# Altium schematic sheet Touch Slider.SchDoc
size A4; Revision: B.2
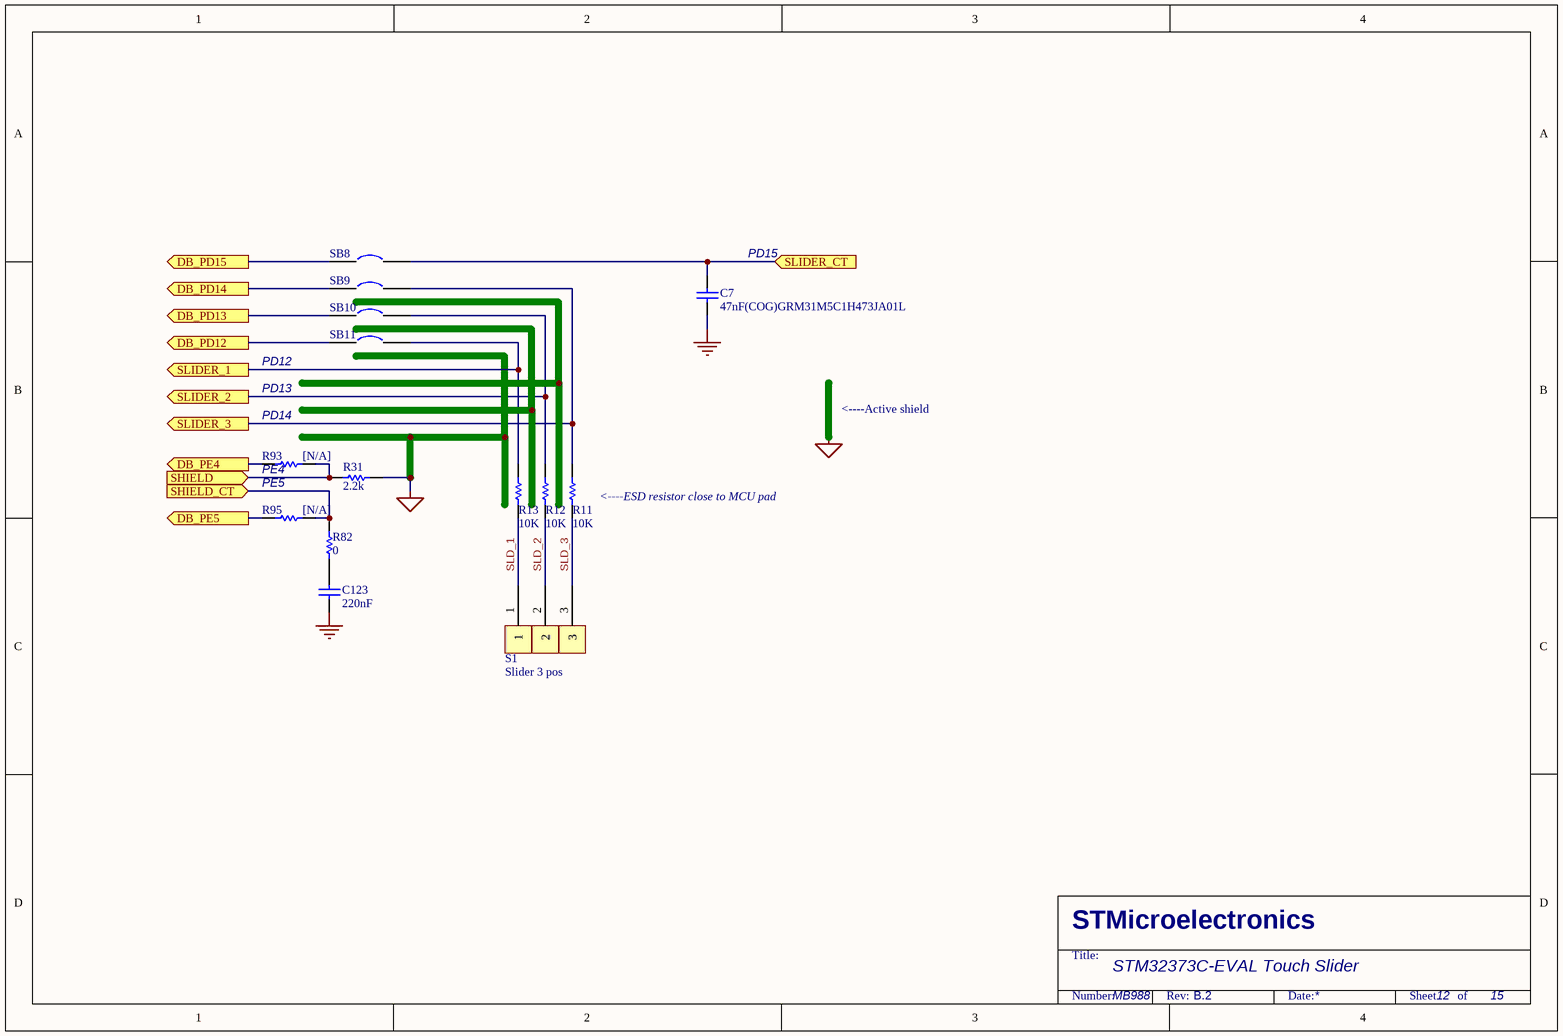
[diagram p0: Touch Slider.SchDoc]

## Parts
C7  47nF(COG)GRM31M5C1H473JA01L  [1206C]
C123  220nF  [0603C]
R11  10K  [0603R]
R12  10K  [0603R]
R13  10K  [0603R]
R31  2.2k  [0603R]
R82  0  [0603R]
R93  [N/A]  [0603R]
R95  [N/A]  [0603R]
S1  Slider 3 pos  [SLIDER3-2(50)]
SB8  (no value)  [JP2_SMD]
SB9  (no value)  [JP2_SMD]
SB10  (no value)  [JP2_SMD]
SB11  (no value)  [JP2_SMD]

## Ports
DB_PD12 (out), DB_PD13 (out), DB_PD14 (out), DB_PD15 (out), DB_PE4 (out), DB_PE5 (out), SHIELD (in), SHIELD_CT (in), SLIDER_1 (out), SLIDER_2 (out), SLIDER_3 (out), SLIDER_CT (in)

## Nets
GND: C7.1 C123.1
TS_SHIELD: R31.2
DB_PD12: SB11.1 ; port DB_PD12
DB_PD13: SB10.1 ; port DB_PD13
DB_PD14: SB9.1 ; port DB_PD14
DB_PD15: SB8.1 ; port DB_PD15
DB_PE4: R93.2 ; port DB_PE4
DB_PE5: R95.2 ; port DB_PE5
SHIELD: R31.1 R93.1 ; port SHIELD
SHIELD_CT: R82.1 R95.1 ; port SHIELD_CT
SLD_1: R13.2 S1.1
SLD_2: R12.2 S1.2
SLD_3: R11.2 S1.3
SLIDER_1: R13.1 SB11.2 ; port SLIDER_1
SLIDER_2: R12.1 SB10.2 ; port SLIDER_2
SLIDER_3: R11.1 SB9.2 ; port SLIDER_3
SLIDER_CT: C7.2 SB8.2 ; port SLIDER_CT
NetC123_2: C123.2 R82.2

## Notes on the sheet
- (near C7) PD15
- PD12
- PD13
- (near R93) PD14
- <----Active shield
- (near R93) PE4
- (near R93) PE5
- (near R11) <----ESD resistor close to MCU pad
- STM32373C-EVAL Touch Slider
- MB988
- 12
- 15

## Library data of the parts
C7 C123 = CAP: Capacitor; Value: 100pF
R11-R13 = res1: Resistor; Value: 1K
R31 R82 R93 R95 = Res1: Resistor; Value: 1K
S1 = Slider 3 pos: plan de cuivre recouvert de vernis + Couche Plastic
SB8-SB11 = Circuit Breaker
